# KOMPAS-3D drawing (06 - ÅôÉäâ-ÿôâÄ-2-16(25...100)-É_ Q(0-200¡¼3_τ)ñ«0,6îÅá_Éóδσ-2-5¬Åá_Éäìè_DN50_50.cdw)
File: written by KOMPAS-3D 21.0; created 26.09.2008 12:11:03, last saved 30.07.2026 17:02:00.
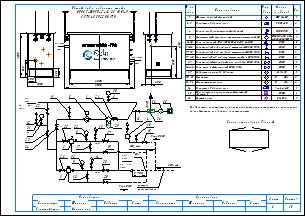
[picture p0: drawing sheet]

Sheets 1-2: A3, landscape

Document properties: Наименование: Макро:21; Автор: RaskoAdmin; Форматы листов документа: 2xA3; Полное имя файла: \\UR38nt01\Departments\КТО\КБ ПУРДГ\Заявки\Прайс-лист на типовые шкафы ГРПШ\ПУРДГ_стандарт_30_04_2026\ПУРДГ с РДНК\ПУРДГ-ШУГО-2-16(25...100)-Р_ Q(0-200нм3_ч)до0,6МПа_Рвых-2-5кПа_РДНК_DN50_50.cdw

Title block, sheet 1: Наименование: Пункт учета газа / ПУГ-Ш-400-Р / ЛГТИ.485922.001ТУ; designation: ЛГТИ.03.4411141; sheet number: 1; Количество листов документа: 2; organisation: ООО "ЭЛЬСТЕР Газэлектроника"; Форматы листов документа: A3; stored path: C:\Рабочие документы\Компас\ПУГ\Схема.cdw; Разработал: Устинов; Проверил: Кошкин; Утвердил: Кошкин
Title block, sheet 2: sheet number: 2; stored path: D:\Рабочие документы\Заявки\ПУРДГ\ПУРДГ-ШУЭО-2-100-Р 4411220.cdw; designation, second copy: ЛГТИ.03.4411141-

Views: Вид 1, Вид 2
Referenced files: wcvoit.frw
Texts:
  Normal
  № на
  схеме
  Усл.
  обозн.
  Марка
  (модель)
  Кол.
  Фильтр газовый фланцевый
  ФГ 16-50
  Регулятор давления газа
  РДНК-50
  Клапан предохранительный сбросной
  КПС DN20
  Измерительный комплекс с ротационным счетчиком Ду50
  СГ-ЭК-Р-(0,2...2,0)-
  Кран кнопочный VE-РАСКО-НЗ-1,6-G1/2-М20
  DN15
  Кран шаровой "под приварку" штуцерный DN20 PN16
  DN20
  Кран шаровой "под приварку" штуцерный DN15 PN16
  Кран шаровой "под приварку" штуцерный п/п DN15 PN16
  Кран шаровой фланцевый с мех. приводом DN50 PN16
  Кран шаровой фланцевый DN50 PN16
  DN50
  Индикатор перепада давления
  Манометр
  Манометр-напоромер
  Обогреватель газогорелочный шкафной
  (Эльтон")
  Счетчик газа
  Delta 15
  0...     МПа
  0...     кПа
  Venio-A-15
  ОГШН
  BK-G1,6
  Общий вид и габариты шкафа
  ПУРДГ-ШУГО-2-16(25...100)-Р
  Выход газа
  Вход газа
  logo-rasko-ge.png
  DN 1
  местное
  сопротивление
  Римп DN15
  Римп DN20
  Выход
  газа
  Р=     кПа
  Вход
  Р=       МПа
  PDI
  Схема открывания дверей
  Предприятие изготовитель может заменять комплектующие на аналогичные,
  не ухудшающие заявленных характеристик.
  Должность
  Конструктор
  Фамилия
  Подпись
  Дата
  Согласовано
  Максимкин
  Лист
  Листов
  POLYLINE_STYLE_0.18_RGB_0_0_0
  POLYLINE_STYLE_0.50_RGB_0_0_0
  POLYLINE_STYLE_0.34_RGB_0_0_0
  PHANTOM_RGB_0_0_0_SC_1_THICK_0.18
  K5LT_THIN_RGB_0_0_0_THICK_0.18
  K5LT32769_RGB_0_0_0_THICK_0.18
  K5LT12_RGB_0_0_0_SC_1_THICK_0.18
  K5LT_DASHED_RGB_0_0_0_SC_1_THICK_0.18
  ACISOTGL_RGB_0_0_0_SC_0.8_THICK_0.25
  CONTINUOUS_RGB_0_127_31_THICK_0.3
  CONTINUOUS_RGB_0_0_255_THICK_0.35
  CONTINUOUS_RGB_255_0_0_THICK_0.35
  POLYLINE_STYLE_0.25_RGB_0_0_0
  CONTINUOUS_RGB_0_0_0_THICK_0.5
  POLYLINE_STYLE_0.35_RGB_0_0_255
  CONTINUOUS_RGB_0_0_0_THICK_0.4
  CONTINUOUS_RGB_0_0_0_THICK_0.35
  НЕВИДИМАЯ_RGB_0_0_0_SC_0.3_THICK_0.25
  СONTINUOUS_RGB_0_0_0_THICK_0.25
  ОСЕВАЯ2_RGB_248_153_30_SC_0.3_THICK_0.25
  Без оформления
Dimensions and other numbers on the sheet: 1; 2, 3; 2; 4; 5; 6-10; 11-16; 6; 17, 18; 19, 20; 21; 22-28; 7; 29; 30, 31; 32, 33; 34; 35; 36; 1500; 250; 300; 1050; 550; 305; 2000; 4130; 2300; 5,,,7DN 1; 31; 12; 22; 23; 24; 11; 30; 25; 32; 8; 17; 13; 27; 19; 10; 15; 26; 33; 9; 3; 18; 14; 28; 20; 16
